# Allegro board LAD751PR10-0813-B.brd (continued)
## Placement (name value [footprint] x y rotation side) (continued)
CG267  22U_0603_6.3V6M  [C_0603]  271.98 90.9 180 top
CG268  22U_0603_6.3V6M  [C_0603]  263.22 55.21 270 bottom
CG269  10U_0603_6.3V6M  [C_0603]  271.41 112.87 180 top
CG270  10U_0603_6.3V6M  [C_0603]  234.9 88.04 90 top
CG271  10U_0603_6.3V6M  [C_0603]  247.21 50.26 0 bottom
CG272  1U_0402_6.3V4Z  [C_0402]  235.53 79.33 90 top
CG273  1U_0402_6.3V4Z  [C_0402]  245.17 50.32 0 bottom
CG274  1U_0402_6.3V4Z  [C_0402]  192.97 68.36 0 bottom
CG275  1U_0402_6.3V4Z  [C_0402]  223.29 77.69 180 top
CG276  1U_0402_6.3V4Z  [C_0402]  190.57 77.2 270 bottom
CG277  1U_0402_6.3V4Z  [C_0402]  193.32 83.34 180 bottom
CG278  22U_0603_6.3V6M  [C_0603]  231.78 54.39 270 bottom
CG279  22U_0603_6.3V6M  [C_0603]  263.22 65.5 90 bottom
CG280  22U_0603_6.3V6M  [C_0603]  263.22 64.48 270 bottom
CG281  10U_0603_6.3V6M  [C_0603]  285.19 78.39 270 bottom
CG282  10U_0603_6.3V6M  [C_0603]  254.33 50.2 180 bottom
CG283  10U_0603_6.3V6M  [C_0603]  204.22 86.27 0 bottom
CG284  1U_0402_6.3V4Z  [C_0402]  193.67 102.39 0 bottom
CG285  1U_0402_6.3V4Z  [C_0402]  196.36 68.36 180 bottom
CG286  1U_0402_6.3V4Z  [C_0402]  224.24 50.32 180 bottom
CG287  1U_0402_6.3V4Z  [C_0402]  196.36 102.39 180 bottom
CG288  22U_0603_6.3V6M  [C_0603]  194.19 113.06 180 bottom
CG289  10U_0603_6.3V6M  [C_0603]  192.62 109.54 270 bottom
CG290  10U_0603_6.3V6M  [C_0603]  230.26 116.68 90 top
CG291  4.7U_0402_6.3V6M  [C_0402]  227.21 108.82 270 top
CG292  1U_0402_6.3V4Z  [C_0402]  192.78 111.13 90 bottom
CG293  0.1U_0201_6.3V6K  [C_0201]  194.18 108.77 270 bottom
CG294  0.1U_0201_6.3V6K  [C_0201]  192.3 110.45 180 bottom
CG295  4.7U_0402_6.3V6M  [C_0402]  220.54 102.19 90 top
CG296  4.7U_0402_6.3V6M  [C_0402]  218.06 105.63 0 top
CG297  4.7U_0402_6.3V6M  [C_0402]  236.8 108.57 270 top
CG298  1U_0402_6.3V4Z  [C_0402]  219.59 102.19 90 top
CG299  1U_0402_6.3V4Z  [C_0402]  221.32 106.9 180 top
CG300  1U_0402_6.3V4Z  [C_0402]  237.88 108.57 270 top
CG301  0.1U_0201_6.3V6K  [C_0201]  239.02 110.55 90 top
CG302  0.1U_0201_6.3V6K  [C_0201]  220.48 104.71 90 top
CG303  0.1U_0201_6.3V6K  [C_0201]  221.59 108.36 0 top
CG304  0.1U_0201_6.3V6K  [C_0201]  239.72 108.4 270 top
CG305  0.1U_0201_6.3V6K  [C_0201]  223.24 104.81 0 top
CG306  0.1U_0201_6.3V6K  [C_0201]  219.85 104.71 90 top
CG307  0.1U_0201_6.3V6K  [C_0201]  220.48 109.15 90 top
CG308  0.1U_0402_10V7K  [C_0402]  241.87 113.25 90 top
CG309  0.1U_0402_10V7K  [C_0402]  242.96 113.39 0 top
CG310  1U_0402_6.3V6K  [C_0402]  230.3 107.93 180 top
CG311  4.7U_0603_6.3V6M  [C_0603]  245.14 111.96 90 top
CG312  0.1U_0402_10V7K  [C_0402]  218.7 102.2 90 top
CG313  0.01U_0402_16V7K  [C_0402]  276.32 101.4 270 top
CG314  0.01U_0402_16V7K  [C_0402]  272.74 102.56 90 top
CG315  0.01U_0402_16V7K  [C_0402]  264.85 60.31 270 bottom
CG316  0.01U_0402_16V7K  [C_0402]  274.6 66.67 180 top
CG317  0.01U_0402_16V7K  [C_0402]  229.4 62.95 180 top
CG318  0.01U_0402_16V7K  [C_0402]  230.93 60.29 0 top
CG320  10U_0402_6.3V6M  [C_0402]  195.03 109.07 270 bottom
CG322  1U_0402_6.3V6K  [C_0402]  196.58 104.03 90 bottom
CG323  0.1U_0402_16V7K  [C_0402]  196.57 106.75 270 bottom
CG324  22U_0402_6.3V6M  [C_0402]  277.73 113.84 270 top
CG325  10U_0402_6.3V4Z  [C_0402]  271.36 109.7 180 top
CG326  10U_0402_6.3V4Z  [C_0402]  270.95 104.26 180 top
CG327  10U_0402_6.3V4Z  [C_0402]  279.32 110.45 180 top
CG328  1U_0402_6.3V4Z  [C_0402]  270.52 117.71 0 top
CG329  1U_0402_6.3V4Z  [C_0402]  273.8 113 0 top
CG330  1U_0402_6.3V4Z  [C_0402]  281.1 110.48 180 top
CG331  1U_0402_6.3V4Z  [C_0402]  273.8 112.06 0 top
CG332  1U_0402_6.3V4Z  [C_0402]  271.36 110.64 180 top
CG333  1U_0402_6.3V4Z  [C_0402]  278.33 104.32 0 top
CG334  1U_0402_6.3V4Z  [C_0402]  281.64 100.16 180 top
CG335  1U_0402_6.3V4Z  [C_0402]  273.03 93.97 0 top
CG336  1U_0402_6.3V4Z  [C_0402]  278.46 99.93 180 top
CG337  1U_0402_6.3V4Z  [C_0402]  272.27 85.99 0 top
CG338  1U_0402_6.3V4Z  [C_0402]  278.46 99.04 180 top
CG339  1U_0402_6.3V4Z  [C_0402]  278.98 93.12 180 top
CG340  1U_0402_6.3V4Z  [C_0402]  271.28 93.99 0 top
CG341  1U_0402_6.3V4Z  [C_0402]  269.54 93.99 0 top
CG342  1U_0402_6.3V4Z  [C_0402]  272.23 98.75 180 top
CG343  1U_0402_6.3V4Z  [C_0402]  270.46 98.74 180 top
CG344  22U_0402_6.3V6M  [C_0402]  262.48 53.7 270 top
CG345  10U_0402_6.3V4Z  [C_0402]  248.71 57.07 270 top
CG346  10U_0402_6.3V4Z  [C_0402]  248.69 54.4 90 top
CG347  10U_0402_6.3V4Z  [C_0402]  256.55 53.74 270 top
CG348  1U_0402_6.3V4Z  [C_0402]  259.67 50.58 180 top
CG349  1U_0402_6.3V4Z  [C_0402]  254.64 53.65 270 top
CG350  1U_0402_6.3V4Z  [C_0402]  256.37 55.76 270 top
CG351  1U_0402_6.3V4Z  [C_0402]  254.63 56.32 90 top
CG352  1U_0402_6.3V4Z  [C_0402]  257.31 64.29 270 top
CG353  1U_0402_6.3V4Z  [C_0402]  253.88 61.69 270 top
CG354  1U_0402_6.3V4Z  [C_0402]  272.12 82.71 0 top
CG355  1U_0402_6.3V4Z  [C_0402]  270.66 82.72 180 top
CG356  1U_0402_6.3V4Z  [C_0402]  269.57 78.07 0 top
CG357  1U_0402_6.3V4Z  [C_0402]  271.4 78.1 0 top
CG358  1U_0402_6.3V4Z  [C_0402]  280.93 69.5 0 top
CG359  1U_0402_6.3V4Z  [C_0402]  271.48 75.66 180 top
CG360  1U_0402_6.3V4Z  [C_0402]  277.61 73.22 270 top
CG361  1U_0402_6.3V4Z  [C_0402]  272.56 69.92 180 top
CG362  1U_0402_6.3V4Z  [C_0402]  275.17 73.12 90 top
CG363  1U_0402_6.3V4Z  [C_0402]  273.22 74.77 180 top
CG364  22U_0402_6.3V6M  [C_0402]  219.07 50.54 180 top
CG365  10U_0402_6.3V4Z  [C_0402]  219.77 61.75 270 top
CG366  10U_0402_6.3V4Z  [C_0402]  215.64 50.46 0 top
CG367  10U_0402_6.3V4Z  [C_0402]  221.38 62.55 270 top
CG368  1U_0402_6.3V4Z  [C_0402]  229.28 64.76 270 bottom
CG369  1U_0402_6.3V4Z  [C_0402]  220.09 55.87 90 top
CG370  1U_0402_6.3V4Z  [C_0402]  215.64 51.37 0 top
CG371  1U_0402_6.3V4Z  [C_0402]  213.79 50.49 0 top
CG372  1U_0402_6.3V4Z  [C_0402]  213.79 51.4 0 top
CG373  1U_0402_6.3V4Z  [C_0402]  223.68 57.84 0 top
CG374  1U_0402_6.3V4Z  [C_0402]  231.82 58.5 90 top
CG375  1U_0402_6.3V4Z  [C_0402]  232.23 64.57 90 top
CG376  1U_0402_6.3V4Z  [C_0402]  232.43 57.25 270 top
CG377  1U_0402_6.3V4Z  [C_0402]  235.1 50.6 180 top
CG378  1U_0402_6.3V4Z  [C_0402]  238.71 62.58 270 top
CG379  1U_0402_6.3V4Z  [C_0402]  238.64 53.77 270 top
CG380  1U_0402_6.3V4Z  [C_0402]  238.72 56.25 270 top
CG381  1U_0402_6.3V4Z  [C_0402]  236.51 57.87 180 top
CG382  1U_0402_6.3V4Z  [C_0402]  231.94 55.38 90 bottom
CG383  1U_0402_6.3V4Z  [C_0402]  232 62.01 270 bottom
CG384  0.1U_0402_10V7K  [C_0402]  194.37 104.15 0 top
CG385  10U_0402_6.3V6M  [C_0402]  197.46 106.75 270 bottom
CG386  0.1U_0402_10V7K  [C_0402]  196.74 114.51 0 bottom
CG387  0.01U_0402_16V7K  [C_0402]  199.25 86.05 90 bottom
CG388  0.01U_0402_16V7K  [C_0402]  200.12 84.49 270 bottom
CG389  22U_0402_6.3V6M  [C_0402]  191.31 99 270 top
CG390  10U_0402_6.3V4Z  [C_0402]  205.23 84.3 0 bottom
CG391  10U_0402_6.3V4Z  [C_0402]  194.64 86.9 180 bottom
CG392  10U_0402_6.3V4Z  [C_0402]  205.23 85.2 0 bottom
CG393  1U_0402_6.3V4Z  [C_0402]  200.87 102.39 180 top
CG394  1U_0402_6.3V4Z  [C_0402]  195.88 95.69 0 top
CG395  1U_0402_6.3V4Z  [C_0402]  202.92 101.42 180 top
CG396  1U_0402_6.3V4Z  [C_0402]  193.93 95.76 180 top
CG397  1U_0402_6.3V4Z  [C_0402]  202.61 94 0 top
CG398  1U_0402_6.3V4Z  [C_0402]  204.48 94.15 0 top
CG399  1U_0402_6.3V4Z  [C_0402]  194.65 67.95 180 top
CG400  1U_0402_6.3V4Z  [C_0402]  190.62 78.99 0 top
CG401  1U_0402_6.3V4Z  [C_0402]  204.9 68.62 0 top
CG402  1U_0402_6.3V4Z  [C_0402]  196.92 75.11 180 top
CG403  1U_0402_6.3V4Z  [C_0402]  197.95 78.77 90 top
CG404  1U_0402_6.3V4Z  [C_0402]  206.75 73.69 180 top
CG405  1U_0402_6.3V4Z  [C_0402]  191.36 73.49 270 top
CG406  1U_0402_6.3V4Z  [C_0402]  201.74 68.73 0 top
CG407  1U_0402_6.3V4Z  [C_0402]  204.02 68.64 90 top
CG408  1U_0402_6.3V4Z  [C_0402]  198.05 68.43 90 top
CG410  22U_0402_6.3V6M  [C_0402]  267.88 90.14 270 top
CG411  22U_0402_6.3V6M  [C_0402]  268.75 90.16 270 top
CG412  22U_0402_6.3V6M  [C_0402]  273.63 91.54 0 top
CG413  10U_0402_6.3V4Z  [C_0402]  278.51 95.66 180 top
CG414  10U_0402_6.3V4Z  [C_0402]  278.45 100.82 180 top
CG415  10U_0402_6.3V4Z  [C_0402]  279.82 93.11 0 top
CG416  1U_0402_6.3V4Z  [C_0402]  270.46 99.64 180 top
CG417  1U_0402_6.3V4Z  [C_0402]  268.63 94.74 90 top
CG418  1U_0402_6.3V4Z  [C_0402]  272.26 85.07 0 top
CG419  1U_0402_6.3V4Z  [C_0402]  271.78 91.95 180 top
CG420  1U_0402_6.3V4Z  [C_0402]  268.54 97.99 270 top
CG421  1U_0402_6.3V4Z  [C_0402]  276.7 94.79 0 top
CG422  1U_0402_6.3V4Z  [C_0402]  273.06 93.08 180 top
CG423  1U_0402_6.3V4Z  [C_0402]  275.64 90.04 90 top
CG424  1U_0402_6.3V4Z  [C_0402]  276.56 90.04 90 top
CG425  1U_0402_6.3V4Z  [C_0402]  269.55 93.01 0 top
CG426  22U_0402_6.3V6M  [C_0402]  259.69 49.69 180 top
CG427  22U_0402_6.3V6M  [C_0402]  263.36 53.71 270 top
CG428  22U_0402_6.3V6M  [C_0402]  255.51 56.32 90 top
CG429  10U_0402_6.3V4Z  [C_0402]  250.62 54.55 270 top
CG430  10U_0402_6.3V4Z  [C_0402]  254.05 50.67 180 top
CG431  10U_0402_6.3V4Z  [C_0402]  256.31 65.26 0 top
CG432  1U_0402_6.3V4Z  [C_0402]  254.69 64.03 90 top
CG433  1U_0402_6.3V4Z  [C_0402]  249.34 63.25 270 top
CG434  1U_0402_6.3V4Z  [C_0402]  263.34 55.51 270 top
CG435  1U_0402_6.3V4Z  [C_0402]  254.77 61.69 270 top
CG436  1U_0402_6.3V4Z  [C_0402]  257.21 50.63 180 top
CG437  1U_0402_6.3V4Z  [C_0402]  257.23 49.74 180 top
CG438  1U_0402_6.3V4Z  [C_0402]  258.83 60.2 180 top
CG439  1U_0402_6.3V4Z  [C_0402]  258.73 57.84 0 top
CG440  1U_0402_6.3V4Z  [C_0402]  254.06 49.78 180 top
CG441  1U_0402_6.3V4Z  [C_0402]  248.45 63.27 270 top
CG442  22U_0402_6.3V6M  [C_0402]  228.38 53.66 270 top
CG443  22U_0402_6.3V6M  [C_0402]  221.42 55.72 90 top
CG444  22U_0402_6.3V6M  [C_0402]  229.28 53.66 270 top
CG445  10U_0402_6.3V4Z  [C_0402]  227.48 55.45 270 top
CG446  10U_0402_6.3V4Z  [C_0402]  228.37 55.43 270 top
CG447  10U_0402_6.3V4Z  [C_0402]  227.5 53.66 270 top
CG448  1U_0402_6.3V4Z  [C_0402]  224.23 50.59 180 top
CG449  1U_0402_6.3V4Z  [C_0402]  222.3 57.51 180 top
CG450  1U_0402_6.3V4Z  [C_0402]  221.32 49.64 0 top
CG451  1U_0402_6.3V4Z  [C_0402]  221.32 50.54 0 top
CG452  1U_0402_6.3V4Z  [C_0402]  220.54 53.99 90 top
CG453  1U_0402_6.3V4Z  [C_0402]  220.35 51.9 180 top
CG454  1U_0402_6.3V4Z  [C_0402]  224.24 49.69 180 top
CG455  1U_0402_6.3V4Z  [C_0402]  221 64.03 90 top
CG456  1U_0402_6.3V4Z  [C_0402]  228.14 57.99 180 top
CG457  1U_0402_6.3V4Z  [C_0402]  221.42 53.98 90 top
CG458  22U_0402_6.3V6M  [C_0402]  201.7 94.06 270 top
CG459  22U_0402_6.3V6M  [C_0402]  197.18 102.01 270 top
CG460  22U_0402_6.3V6M  [C_0402]  192.02 101.78 0 top
CG461  10U_0402_6.3V4Z  [C_0402]  193.96 94.81 180 top
CG462  10U_0402_6.3V4Z  [C_0402]  204.26 95.45 0 top
CG463  10U_0402_6.3V4Z  [C_0402]  201.95 95.68 180 top
CG464  1U_0402_6.3V4Z  [C_0402]  200.14 96.62 270 top
CG465  1U_0402_6.3V4Z  [C_0402]  201.76 102.41 90 top
CG466  1U_0402_6.3V4Z  [C_0402]  202.8 102.31 90 top
CG467  1U_0402_6.3V4Z  [C_0402]  204.85 102.64 180 top
CG468  1U_0402_6.3V4Z  [C_0402]  190.33 91.1 270 top
CG469  1U_0402_6.3V4Z  [C_0402]  192.16 93.89 90 top
CG470  1U_0402_6.3V4Z  [C_0402]  191.3 96.31 90 top
CG471  1U_0402_6.3V4Z  [C_0402]  200.87 103.28 180 top
CG472  1U_0402_6.3V4Z  [C_0402]  198.61 92.64 0 top
CG473  1U_0402_6.3V4Z  [C_0402]  198.54 94.93 180 top
CG474  0.1U_0402_16V4Z  [C_0402]  197.89 111.45 0 top
CG475  0.1U_0402_16V4Z  [C_0402]  196.76 104.46 270 top
CG476  0.1U_0201_6.3V6K  [C_0201]  314.31 60.32 270 top
CG478  0.1U_0201_6.3V6K  [C_0201]  277.36 155.16 90 top
CG479  0.1U_0201_6.3V6K  [C_0201]  280.35 161.33 0 top
CG480  0.1U_0201_6.3V6K  [C_0201]  275.69 147.77 270 top
CG481  2200P_0402_25V7K  [C_0402]  281.64 162.54 180 top
CG482  0.047U_0402_16V4Z  [C_0402]  277.92 162.91 270 top
CG483  0.1U_0201_6.3V6K  [C_0201]  281.21 144.11 270 top
CG487  0.1U_0402_16V7K  [C_0402]  193.16 109.54 180 top
CH3  0.1U_0402_10V7K  [C_0402]  204.15 23.88 270 top
CH4  0.1U_0402_10V7K  [C_0402]  215.31 33.51 270 top
CH45  8.2P_0402_50V  [C_0402]  219.66 37.08 90 bottom
CH46  8.2P_0402_50V  [C_0402]  219.66 36.15 270 bottom
CH47  15P_0402_50V  [C_0402]  193.47 43.49 180 bottom
CH48  15P_0402_50V  [C_0402]  194.35 43.49 0 bottom
CH49  0.1U_0402_16V7K  [C_0402]  229.04 14.32 0 bottom
CH52  1U_0603_10V6K~D  [C_0603]  216.37 32.23 270 top
CH53  1U_0603_10V6K~D  [C_0603]  216.68 41.81 0 top
CH70  0.1U_0402_10V7K  [C_0402]  214.65 27.01 180 top
CH80  1U_0402_6.3V6K~D  [C_0402]  212.61 29.06 180 top
CH82  1U_0402_6.3V6K~D  [C_0402]  203.73 32.84 90 top
CH100  0.022U_0402_25V7K  [C_0402]  152.66 37.58 0 top
CH101  0.022U_0402_25V7K  [C_0402]  155.34 53.57 90 top
CH102  10U_0603_6.3V6M~D  [C_0603]  168.05 105.17 270 top
CH103  10U_0603_6.3V6M~D  [C_0603]  168.05 107.58 270 top
CH104  10U_0603_6.3V6M~D  [C_0603]  167.94 109.98 90 top
CH105  1U_0402_6.3V6K~D  [C_0402]  172.5 114.54 0 top
CH106  1U_0402_6.3V6K~D  [C_0402]  172.5 115.42 0 top
CH107  1U_0402_6.3V6K~D  [C_0402]  167.98 113.21 0 top
CH108  1U_0402_6.3V6K~D  [C_0402]  168.19 114.51 180 top
CH109  1U_0402_6.3V6K~D  [C_0402]  169.48 114.84 0 top
CH110  1U_0402_6.3V6K~D  [C_0402]  167.9 112.31 0 top
CH118  22U_0603_6.3V6M  [C_0603]  146.02 100.47 90 top
CH119  10U_0603_6.3V6M~D  [C_0603]  150.78 99.52 90 top
CH120  22U_0603_6.3V6M  [C_0603]  171.46 99.09 0 top
CH121  22U_0603_6.3V6M  [C_0603]  148.65 79.51 0 top
CH122  10U_0603_6.3V6M~D  [C_0603]  152.49 99.84 90 top
CH123  10U_0603_6.3V6M~D  [C_0603]  148.65 78.24 0 top
CH124  22U_0603_6.3V6M  [C_0603]  144.37 100.47 90 top
CH125  10U_0603_6.3V6M~D  [C_0603]  156.13 99.18 90 top
CH126  10U_0603_6.3V6M~D  [C_0603]  167.9 95.6 90 top
CH127  10U_0603_6.3V6M~D  [C_0603]  165.25 99.77 90 top
CH128  10U_0603_6.3V6M~D  [C_0603]  148.65 76.97 0 top
CH129  22U_0805_6.3V6M~D  [C_0805]  168.15 79.25 0 top
CH130  22U_0805_6.3V6M~D  [C_0805]  168.15 77.54 0 top
CH131  22U_0805_6.3V6M~D  [C_0805]  153.57 77.34 180 top
CH132  22U_0805_6.3V6M~D  [C_0805]  153.57 79.18 180 top
CH173  0.1U_0402_10V7K  [C_0402]  212.61 28.17 180 top
CH174  0.1U_0402_10V  [C_0402]  210.27 35.43 90 top
CH175  0.1U_0402_10V  [C_0402]  214.9 43.11 90 bottom
CH176  1U_0402_6.3V6K~D  [C_0402]  214.14 25.5 180 top
CH177  22U_0805_6.3V6M~D  [C_0805]  203.44 42.07 0 bottom
CH178  22U_0805_6.3V6M~D  [C_0805]  200.33 42.32 0 bottom
CH179  1U_0402_6.3V6K~D  [C_0402]  199.34 41.8 90 bottom
CH180  1U_0402_6.3V6K~D  [C_0402]  198.64 28.4 90 top
CH181  22U_0805_6.3V6M~D  [C_0805]  193.34 26 180 top
CH182  22U_0805_6.3V6M~D  [C_0805]  193.34 27.77 180 top
CH183  1U_0402_6.3V6K~D  [C_0402]  202.19 26.91 270 top
CH184  22U_0805_6.3V6M~D  [C_0805]  193.34 29.53 180 top
CH185  1U_0402_6.3V6K~D  [C_0402]  206.03 30.57 180 top
CH186  0.1U_0402_10V7K  [C_0402]  213.9 30.49 180 top
CH187  1U_0402_6.3V6K~D  [C_0402]  216.85 40.74 0 top
CH188  1U_0402_6.3V6K~D  [C_0402]  206.14 33.79 90 top
CH189  0.1U_0402_10V7K  [C_0402]  210.27 37.78 90 top
CH190  0.1U_0402_10V7K  [C_0402]  206.01 19.6 270 top
CH191  0.1U_0402_10V7K  [C_0402]  209.57 19.28 270 top
CH192  0.1U_0402_10V7K  [C_0402]  215.46 16.45 0 top
CH193  0.1U_0402_16V7K~D  [C_0402]  172.79 100.48 90 top
CH194  0.1U_0402_16V7K~D  [C_0402]  130.9 114.97 180 top
CH195  0.1U_0402_16V7K~D  [C_0402]  132.33 115.48 0 top
CH197  0.1U_0402_10V7K  [C_0402]  125.57 75.89 270 top
CH200  0.1U_0402_10V7K  [C_0402]  213 23.2 270 top
CH201  0.1U_0201_6.3V6K  [C_0201]  216.42 22.28 90 top
CH202  0.22U_0201_6.3V  [C_0201]  247.66 9.39 90 top
CH203  0.22U_0201_6.3V  [C_0201]  248.29 9.39 90 top
CH204  0.22U_0201_6.3V  [C_0201]  329.87 36.23 180 top
CH205  0.22U_0201_6.3V  [C_0201]  329.87 35.59 180 top
CH206  0.22U_0201_6.3V  [C_0201]  331.26 37.12 180 top
CH207  0.22U_0201_6.3V  [C_0201]  331.26 36.48 180 top
CH208  0.22U_0201_6.3V  [C_0201]  250.07 9.39 90 top
CH209  0.22U_0201_6.3V  [C_0201]  250.71 9.39 90 top
CH210  0.22U_0201_6.3V  [C_0201]  237.92 7.78 180 top
CH211  0.22U_0201_6.3V  [C_0201]  237.92 8.41 180 top
CH212  0.22U_0201_6.3V  [C_0201]  239.57 11.08 180 top
CH213  0.22U_0201_6.3V  [C_0201]  239.57 10.45 180 top
CH214  0.22U_0201_6.3V  [C_0201]  269.38 12.24 180 bottom
CH215  0.22U_0201_6.3V  [C_0201]  269.38 11.59 180 bottom
CH216  0.22U_0201_6.3V  [C_0201]  268.78 15.73 180 bottom
CH217  0.22U_0201_6.3V  [C_0201]  268.78 15.09 180 bottom
CH218  0.22U_0201_6.3V  [C_0201]  269.1 20.21 90 bottom
CH219  0.22U_0201_6.3V  [C_0201]  268.46 20.21 90 bottom
CH220  0.22U_0201_6.3V  [C_0201]  268.18 17.2 0 bottom
CH221  0.22U_0201_6.3V  [C_0201]  268.18 17.84 0 bottom
CI38  0.1U_0402_10V6K  [C_0402]  165.68 173.77 90 bottom
CI39  0.1U_0402_10V6K  [C_0402]  166.57 173.77 90 bottom
CL1  0.1U_0402_16V7K  [C_0402]  268.56 163.67 180 bottom
CL2  0.1U_0402_16V7K  [C_0402]  268.56 162.78 180 bottom
CL3  0.1U_0402_16V7K  [C_0402]  271.8 165.88 90 bottom
CL4  0.1U_0402_16V7K  [C_0402]  272.69 165.88 90 bottom
CL5  1U_0402_6.3V6K~D  [C_0402]  275.34 160.46 180 top
CL6  0.1U_0402_16V7K~D  [C_0402]  275.34 159.57 180 top
CL7  0.1U_0402_16V7K~D  [C_0402]  267.38 159.66 180 bottom
CL8  18P_0402_50V8J  [C_0402]  277.8 161 180 bottom
CL9  22P_0402_50V8J  [C_0402]  278.22 162.47 180 bottom
CL11  1000P_0402_50V7K~D  [C_0402]  276.63 165.13 0 bottom
CL12  0.1U_0402_16V7K~D  [C_0402]  269.59 167.02 180 top
CL13  1U_0402_6.3V6K~D  [C_0402]  269.59 166.14 180 top
CL14  10U_0603_6.3V6M~D  [C_0603]  269.77 168.1 180 top
CL15  10U_0603_6.3V6M~D  [C_0603]  269.77 169.37 180 top
CL16  0.1U_0402_16V7K~D  [C_0402]  272.54 157.79 90 top
CL17  1U_0402_6.3V6K~D  [C_0402]  274.3 157.79 90 top
CL18  1U_0402_6.3V6K~D  [C_0402]  275.34 161.35 180 top
CL19  0.1U_0402_16V7K~D  [C_0402]  275.34 162.24 180 top
CL20  0.1U_0402_16V7K~D  [C_0402]  271.6 164.6 270 top
CL21  1U_0402_6.3V6K~D  [C_0402]  270.71 164.6 270 top
CL22  4.7U_0603_6.3V6K~D  [C_0603]  272.51 165.51 90 top
CL23  0.1U_0402_16V7K~D  [C_0402]  269.82 164.6 270 top
CL24  0.1U_0402_16V7K~D  [C_0402]  273.43 157.79 90 top
CL25  0.1U_0402_16V7K~D  [C_0402]  271.65 157.79 90 top
CL27  470P_0402_50V7K  [C_0402]  242.71 170.03 270 top
CL28  470P_0402_50V7K  [C_0402]  263.47 158.41 270 top
CL29  470P_0402_50V7K  [C_0402]  264.36 158.41 270 top
CL30  10P_1808_3KV7K~D  [C_1808]  263.03 158.66 90 bottom
CL31  470P_0402_50V7K  [C_0402]  266.12 159.8 0 top
CL32  1000P_0402_50V7K~D  [C_0402]  250.83 156.76 270 top
CL33  0.1U_0402_16V7K~D  [C_0402]  247.91 155.85 90 top
CL34  1000P_0402_50V7K~D  [C_0402]  247.02 156.76 270 top
CL35  0.1U_0402_16V7K~D  [C_0402]  249.94 155.85 90 top
CL36  1000P_0402_50V7K~D  [C_0402]  254.96 156.76 270 top
CL37  0.1U_0402_16V7K~D  [C_0402]  255.85 155.85 90 top
CL38  1000P_0402_50V7K~D  [C_0402]  257.44 156.76 270 top
CL39  0.1U_0402_16V7K~D  [C_0402]  258.33 155.85 90 top
CL40  4.7U_0805_10V4Z  [C_0805]  269.97 171.67 180 bottom
CL41  0.1U_0402_16V7K  [C_0402]  271.03 171.22 90 bottom
CL42  0.1U_0402_16V7K  [C_0402]  266.96 170.29 270 bottom
CL43  1U_0402_6.3V6K~D  [C_0402]  273.38 164.6 270 top
CL44  0.1U_0402_16V7K~D  [C_0402]  272.49 164.6 270 top
CLRP1  SHORT PADS  [SHORTPADS]  173.94 34.07 90 bottom
CM9  0.1U_0402_10V7K  [C_0402]  134.11 160.39 90 bottom
CM10  0.1U_0402_10V7K  [C_0402]  302.88 41.99 90 top
CM11  4.7U_0805_10V4Z  [C_0805]  314.23 42.07 180 top
CM12  22U_0603_6.3V6M~D  [C_0603]  301.8 40.79 90 top
CM13  0.1U_0402_10V7K~D  [C_0402]  300.72 40.78 90 top
CM14  22U_0603_6.3V6M~D  [C_0603]  315.54 41.37 90 top
CM15  0.1U_0402_10V7K~D  [C_0402]  315.73 40.18 270 top
CM16  0.1U_0402_10V7K  [C_0402]  172.4 159.42 0 bottom
CM17  0.1U_0402_10V7K  [C_0402]  172.4 160.31 0 bottom
CM18  0.1U_0402_10V7K  [C_0402]  168.41 161.37 90 bottom
CM19  22U_0603_6.3V6M  [C_0603]  164.16 160.5 270 bottom
CM20  0.1U_0402_10V7K  [C_0402]  168.34 152.36 270 bottom
CM21  1U_0402_6.3V  [C_0402]  165.99 152.36 270 bottom
CM23  0.1U_0402_10V7K  [C_0402]  162.25 174.49 270 bottom
CM29  10U_0603_6.3V6M  [C_0603]  125.98 151.39 0 top
CM30  1U_0402_6.3V  [C_0402]  125.23 155.2 180 bottom
CM31  10U_0603_6.3V6M  [C_0603]  125.98 153.17 0 top
CM32  0.1U_0402_10V7K  [C_0402]  131.12 151.47 270 bottom
CM33  1U_0402_6.3V  [C_0402]  125.23 156.09 180 bottom
CM34  0.1U_0402_10V7K  [C_0402]  138.43 155.54 0 bottom
CM35  0.1U_0402_10V7K  [C_0402]  129.6 151.47 270 bottom
CM36  0.1U_0402_10V7K  [C_0402]  130.74 160.39 90 bottom
CM62  0.22U_0201_6.3V  [C_0201]  133.22 148.65 90 bottom
CM63  0.22U_0201_6.3V  [C_0201]  132.97 150.55 90 bottom
CM64  0.22U_0201_6.3V  [C_0201]  136.9 148.65 90 bottom
CM65  0.22U_0201_6.3V  [C_0201]  136.01 148.65 90 bottom
CM66  0.22U_0201_6.3V  [C_0201]  132.08 150.55 90 bottom
CM67  0.22U_0201_6.3V  [C_0201]  135.57 150.55 90 bottom
CM68  0.22U_0201_6.3V  [C_0201]  134.11 148.65 90 bottom
CM69  0.22U_0201_6.3V  [C_0201]  134.68 150.55 90 bottom
CM70  0.1U_0402_10V7K  [C_0402]  149.61 170.92 270 bottom
CM98  0.01U_0402_16V7K  [C_0402]  163.36 162.85 180 bottom
CM99  0.01U_0402_16V7K  [C_0402]  163.36 161.68 180 bottom
CN9  1U_0402_10V6K  [C_0402]  312.81 39.28 90 top
CN23  0.1U_0402_16V7K  [C_0402]  314.32 37.69 180 top
CN24  0.1U_0402_16V7K  [C_0402]  314.32 36.66 180 top
CN25  1U_0402_10V6K  [C_0402]  316.67 36.96 0 top
CPU1  SKL-H_BGA1440  [SKL-H_BGA_1440P-T]  172.98 93.59 270 bottom
CS1  10U_0603_25V6M  [C_0603]  127.45 10.13 270 top
CS2  10U_0603_6.3V6M  [C_0603]  183.99 62.45 180 top
CS5  1000P_0402_50V7K~D  [C_0402]  125.48 10.14 270 top
CS6  0.1U_0402_25V6K~D  [C_0402]  126.37 10.14 270 top
CS7  0.1U_0402_16V4Z  [C_0402]  182.58 66.2 180 top
CS16  22U_0402_6.3V6M  [C_0402]  125.68 11.45 90 top
CT1  0.22U_0201_6.3V  [C_0201]  188.35 162.61 180 top
CT2  0.22U_0201_6.3V  [C_0201]  188.35 163.18 180 top
CT3  0.22U_0201_6.3V  [C_0201]  188.35 160.32 180 top
CT4  0.22U_0201_6.3V  [C_0201]  188.35 164.32 180 top
CT5  0.22U_0201_6.3V  [C_0201]  188.35 166.61 180 top
CT6  0.1U_0201_6.3V6K  [C_0201]  177.42 157.43 90 top
CT7  0.1U_0201_6.3V6K  [C_0201]  177.99 157.43 90 top
CT8  0.1U_0201_6.3V6K  [C_0201]  179.14 157.43 90 top
CT9  0.1U_0201_6.3V6K  [C_0201]  178.57 157.43 90 top
CT10  0.1U_0201_6.3V6K  [C_0201]  180.28 157.43 90 top
CT11  0.1U_0201_6.3V6K  [C_0201]  181.42 157.43 90 top
CT12  0.22U_0201_6.3V  [C_0201]  188.35 163.75 180 top
CT13  0.22U_0201_6.3V  [C_0201]  188.35 162.04 180 top
CT14  0.22U_0201_6.3V  [C_0201]  188.35 161.47 180 top
CT15  0.22U_0201_6.3V  [C_0201]  188.35 159.75 180 top
CT16  0.22U_0201_6.3V  [C_0201]  188.35 160.89 180 top
CT18  0.22U_0201_6.3V  [C_0201]  188.35 164.9 180 top
CT21  0.22U_0201_6.3V  [C_0201]  188.35 167.18 180 top
CT23  0.1U_0201_6.3V6K  [C_0201]  179.71 157.43 90 top
CT24  0.1U_0201_6.3V6K  [C_0201]  180.85 157.43 90 top
CT25  0.1U_0201_6.3V6K  [C_0201]  179.39 152.69 90 bottom
CT26  0.1U_0201_6.3V6K  [C_0201]  178.82 152.69 90 bottom
CT27  0.1U_0201_6.3V6K  [C_0201]  182.57 157.43 90 top
CT28  0.1U_0201_6.3V6K  [C_0201]  182 157.43 90 top
CT29  0.1U_0201_6.3V6K  [C_0201]  183.71 157.43 90 top
CT30  0.1U_0201_6.3V6K  [C_0201]  183.14 157.43 90 top
CT31  0.1U_0201_6.3V6K  [C_0201]  184.85 157.43 90 top
CT32  0.1U_0201_6.3V6K  [C_0201]  184.28 157.43 90 top
CT33  0.1U_0201_6.3V6K  [C_0201]  186 157.43 90 top
CT34  0.1U_0201_6.3V6K  [C_0201]  185.42 157.43 90 top
CT35  0.1U_0201_6.3V6K  [C_0201]  181.35 152.69 90 bottom
CT36  0.1U_0201_6.3V6K  [C_0201]  181.95 152.68 90 bottom
CT37  12P_0402_50V8J  [C_0402]  190.84 170.34 180 top
CT38  12P_0402_50V8J  [C_0402]  190.52 168.82 180 top
CT39  0.22U_0201_6.3V  [C_0201]  183.15 172.68 270 top
CT40  0.22U_0201_6.3V  [C_0201]  182.58 172.68 270 top
CT41  0.22U_0201_6.3V  [C_0201]  184.04 172.68 270 top
CT42  0.22U_0201_6.3V  [C_0201]  184.61 172.68 270 top
CT43  0.1U_0201_6.3V6K  [C_0201]  182.62 159.67 90 bottom
CT44  0.1U_0201_6.3V6K  [C_0201]  182.05 159.67 90 bottom
CT45  0.1U_0201_6.3V6K  [C_0201]  188.67 154.41 270 bottom
CT46  0.1U_0201_6.3V6K  [C_0201]  178.75 162.54 270 bottom
CT47  1U_0201_6.3V6M  [C_0201]  178.11 167.68 270 bottom
CT48  1U_0201_6.3V6M  [C_0201]  181.9 163.74 0 bottom
CT49  1U_0201_6.3V6M  [C_0201]  176.43 172.12 180 top
CT50  10U_0402_6.3V6M  [C_0402]  176.87 172.88 180 top
CT51  10U_0402_6.3V6M  [C_0402]  176.87 173.77 180 top
CT52  10U_0402_6.3V6M  [C_0402]  176.87 174.66 180 top
CT53  10U_0402_6.3V6M  [C_0402]  177.73 174.66 0 top
CT54  1U_0201_6.3V6M  [C_0201]  180.03 165.04 270 bottom
CT55  1U_0201_6.3V6M  [C_0201]  184.57 163.8 0 bottom
CT56  1U_0201_6.3V6M  [C_0201]  187.18 158.05 180 top
CT57  1U_0201_6.3V6M  [C_0201]  175.45 153.02 270 bottom
CT58  1U_0201_6.3V6M  [C_0201]  174.81 153.02 270 bottom
CT59  1U_0201_6.3V6M  [C_0201]  181.29 165.21 270 bottom
CT60  1U_0201_6.3V6M  [C_0201]  181.86 162.53 270 bottom
CT61  1U_0201_6.3V6M  [C_0201]  179.38 165.02 270 bottom
CT62  1U_0201_6.3V6M  [C_0201]  178.6 165.68 180 bottom
CT63  1U_0201_6.3V6M  [C_0201]  179.4 168.6 270 bottom
CT64  1U_0201_6.3V6M  [C_0201]  180.41 169.22 90 bottom
CT65  1U_0201_6.3V6M  [C_0201]  179.84 169.22 90 bottom
CT66  1U_0201_6.3V6M  [C_0201]  180.98 169.22 90 bottom
CT67  1U_0201_6.3V6M  [C_0201]  179.24 169.81 180 bottom
CT68  1U_0201_6.3V6M  [C_0201]  179.24 169.23 180 bottom
CT69  1U_0201_6.3V6M  [C_0201]  181.56 169.22 90 bottom
CT70  1U_0201_6.3V6M  [C_0201]  187.8 157.99 0 top
CT71  1U_0201_6.3V6M  [C_0201]  183.93 164.43 0 bottom
CT72  1U_0201_6.3V6M  [C_0201]  183.12 164.43 180 bottom
CT73  47U_0603_6.3V6M  [C_0603]  173.21 173.14 90 bottom
CT74  47U_0603_6.3V6M  [C_0603]  171.88 173.14 90 bottom
CT75  47U_0603_6.3V6M  [C_0603]  170.54 173.14 90 bottom
CT77  1U_0201_6.3V6M  [C_0201]  183.17 162.57 0 bottom
CT78  1U_0201_6.3V6M  [C_0201]  179.38 162.54 270 bottom
CT79  1U_0201_6.3V6M  [C_0201]  181.29 163.42 90 bottom
CT80  1U_0201_6.3V6M  [C_0201]  180.03 163.25 90 bottom
CT81  10U_0402_6.3V6M  [C_0402]  183.54 168.8 90 bottom
CT82  10U_0402_6.3V6M  [C_0402]  182.65 168.8 90 bottom
CT83  1U_0201_6.3V6M  [C_0201]  181.15 167.16 180 bottom
CT84  1U_0201_6.3V6M  [C_0201]  183.42 166.97 0 bottom
CT85  1U_0201_6.3V6M  [C_0201]  183.97 166.25 270 bottom
CT86  1U_0201_6.3V6M  [C_0201]  182.63 166.33 90 bottom
CT88  0.1U_0402_10V6K  [C_0402]  195.6 163.67 180 top
CT90  22U_0603_6.3V6M  [C_0603]  203.83 158.31 180 bottom
CT91  22U_0603_6.3V6M  [C_0603]  203.83 157.05 180 bottom
CT92  22U_0603_6.3V6M  [C_0603]  204.72 160.15 0 bottom
CT93  22U_0603_6.3V6M  [C_0603]  204.72 161.36 0 bottom
CT94  0.47U_0402_25V6K  [C_0402]  194.9 179.55 180 top
CT95  0.47U_0402_25V6K  [C_0402]  190.31 177.95 0 top
CT96  0.47U_0402_25V6K  [C_0402]  193.18 177.62 0 top
CT97  0.47U_0402_25V6K  [C_0402]  191.28 179.59 180 top
CT98  2.2U_0603_16V6K  [C_0603]  195.97 161.26 180 bottom
CT99  4.7U_0603_10V6K  [C_0603]  197.56 158.02 180 bottom
CT100  4.7U_0603_10V6K  [C_0603]  198.26 165.13 90 top
CT101  1U_0402_6.3V6K  [C_0402]  197.1 164.18 0 top
CT102  1U_0201_6.3V6M  [C_0201]  196.22 167.47 90 top
CT103  10U_0402_6.3V6M  [C_0402]  195.6 162.34 180 bottom
CT104  0.22U_0402_10V4Z  [C_0402]  202.63 167.19 90 bottom
CT106  1U_0603_25V6K  [C_0603]  204.61 160.94 180 top
CT108  0.22U_0201_6.3V  [C_0201]  188.35 166.04 180 top
CT109  0.22U_0201_6.3V  [C_0201]  188.35 165.47 180 top
CT110  0.22U_0201_6.3V  [C_0201]  188.35 167.75 180 top
CT111  0.22U_0201_6.3V  [C_0201]  188.35 168.32 180 top
CT112  220P_0201_25V7K  [C_0201]  202.95 165.78 270 top
CT113  220P_0201_25V7K  [C_0201]  203.75 166.41 270 top
CU2  47U_0805_6.3V6M  [C_0805]  19.92 43.59 0 bottom
CU3  10U_0603_6.3V6M~D  [C_0603]  20.07 42.13 0 bottom
CU6  150U_B15G_6.3VM_R70M  [C_B15G]  20.48 46.07 0 bottom
CU7  0.1U_0402_16V7K  [C_0402]  20.38 41.6 180 top
CU10  47U_0805_6.3V6M  [C_0805]  321.88 20.59 90 top
CU11  10U_0603_6.3V6M~D  [C_0603]  319.97 20.17 180 top
CU12  0.1U_0402_10V7K  [C_0402]  24.16 39.69 0 top
CU13  0.1U_0402_10V7K  [C_0402]  24.16 38.8 0 top
CU16  0.1U_0402_16V7K  [C_0402]  318.46 24.87 180 top
CU17  0.1U_0402_16V7K  [C_0402]  319.39 24.87 0 top
CU18  0.47U_0402_25V6K  [C_0402]  11.06 63.15 90 bottom
CU19  0.47U_0402_25V6K  [C_0402]  11.95 57.31 0 bottom
CU20  0.47U_0402_25V6K  [C_0402]  11.06 62.26 270 bottom
CU21  0.47U_0402_25V6K  [C_0402]  11.06 57.83 270 bottom
CU26  0.1U_0402_16V7K  [C_0402]  27.92 42.74 0 top
CU27  2.2U_0603_6.3V6K  [C_0603]  31.68 44.2 90 top
CU28  0.1U_0402_16V7K  [C_0402]  32.81 47.14 180 top
CU29  0.1U_0402_16V7K  [C_0402]  29.7 46.23 0 top
CU30  0.1U_0402_10V7K  [C_0402]  14.51 61.93 0 top
CU31  0.1U_0402_10V7K  [C_0402]  14.51 62.88 0 top
CU32  2.2U_0603_25V6K  [C_0603]  14.5 54.16 90 bottom
CU33  47U_0603_6.3V6M  [C_0603]  22.63 53.5 90 bottom
CU34  0.1U_0402_16V7K  [C_0402]  22.92 51.15 0 bottom
CU35  0.1U_0402_16V7K  [C_0402]  20.77 50.65 270 bottom
CU37  10U_0805_25V6K  [C_0805]  12.91 54.26 90 bottom
CU38  0.1U_0402_10V7K  [C_0402]  14.74 58.47 0 top
CU39  0.1U_0402_10V7K  [C_0402]  14.74 57.58 0 top
CU40  150U_B15G_6.3VM_R70M  [C_B15G]  13.08 52.08 270 bottom
CU42  47U_0603_6.3V6M  [C_0603]  22.23 50.07 0 bottom
CU44  47U_0603_6.3V6M  [C_0603]  21.41 53.5 90 bottom
CU45  0.1U_0402_10V7K  [C_0402]  321.71 19.58 0 top
CU46  0.1U_0402_10V7K  [C_0402]  315.3 23.49 90 top
CU47  0.1U_0402_10V7K  [C_0402]  21.46 47.59 90 top
CU48  10U_0402_6.3V6M  [C_0402]  316.2 23.5 90 top
CV1  0.1U_0201_6.3V6K  [C_0201]  147.07 167.27 270 top
CV2  0.1U_0201_6.3V6K  [C_0201]  147.71 167.27 270 top
CV3  0.1U_0201_6.3V6K  [C_0201]  148.41 167.58 270 top
CV4  0.1U_0201_6.3V6K  [C_0201]  149.04 167.58 270 top
CV5  4.7U_0805_10V4Z  [C_0805]  161.93 164.73 90 bottom
CV6  0.1U_0201_6.3V6K  [C_0201]  150.31 167.58 270 top
CV7  0.1U_0201_6.3V6K  [C_0201]  150.57 166.19 270 top
CV8  0.1U_0201_6.3V6K  [C_0201]  149.68 167.58 270 top
CV9  0.1U_0402_10V7K  [C_0402]  164.47 169.98 0 bottom
CV10  4.7U_0805_10V4Z  [C_0805]  163.09 169.34 180 bottom
CV11  0.1U_0201_6.3V6K  [C_0201]  151.2 166.19 270 top
CV12  0.1U_0201_6.3V6K  [C_0201]  151.52 167.58 270 top
CV13  0.1U_0201_6.3V6K  [C_0201]  152.15 167.58 270 top
CV14  0.1U_0603_25V7K  [C_0603]  173.1 182.4 0 top
CV15  1000P_0402_50V7K  [C_0402]  152.79 168.32 270 bottom
CV17  0.1U_0402_10V7K  [C_0402]  164.47 169.03 0 bottom
CV18  10U_0603_6.3V6M  [C_0603]  162.89 167.86 180 bottom
CV19  0.1U_0402_10V7K  [C_0402]  166.98 171.9 180 bottom
CV20  0.1U_0402_16V7K  [C_0402]  223.11 160.04 90 bottom
CV21  4.7U_0805_10V4Z  [C_0805]  166.72 169.89 270 bottom
CV23  0.1U_0201_6.3V6K  [C_0201]  243.66 159.89 90 top
CV24  0.1U_0201_6.3V6K  [C_0201]  226.42 160.43 270 bottom
CV25  0.1U_0201_6.3V6K  [C_0201]  225.85 160.43 270 bottom
CV26  0.1U_0201_6.3V6K  [C_0201]  230.28 166.68 90 bottom
CV27  0.1U_0201_6.3V6K  [C_0201]  229.33 166.68 90 bottom
CV28  0.1U_0201_6.3V6K  [C_0201]  241.48 167.51 90 top
CV29  0.1U_0201_6.3V6K  [C_0201]  234.7 167.57 90 bottom
CV30  0.1U_0201_6.3V6K  [C_0201]  242.37 167.51 90 top
CV31  0.1U_0201_6.3V6K  [C_0201]  235.45 167.57 90 bottom
CV32  0.1U_0201_6.3V6K  [C_0201]  241.65 166.68 90 bottom
CV33  0.1U_0201_6.3V6K  [C_0201]  240.76 166.68 90 bottom
CV34  10U_0402_6.3V6M  [C_0402]  238.73 167.04 180 bottom
CV35  0.1U_0201_6.3V6K  [C_0201]  238.68 167.8 180 bottom
CV372  10P_0402_50V8J  [C_0402]  162.39 163.72 180 bottom
CV373  10P_0402_50V8J  [C_0402]  164.47 168.08 0 bottom
CV374  10P_0402_50V8J  [C_0402]  164.21 162.78 0 top
CV375  10P_0402_50V8J  [C_0402]  171.79 182.4 180 top
CV416  0.1U_0201_6.3V6K  [C_0201]  202.57 127.71 270 bottom
CV417  0.1U_0201_6.3V6K  [C_0201]  202 127.71 270 bottom
CV418  0.1U_0201_6.3V6K  [C_0201]  201.43 127.71 270 bottom
CV419  0.1U_0201_6.3V6K  [C_0201]  200.86 127.71 270 bottom
CV420  0.1U_0201_6.3V6K  [C_0201]  200.29 127.71 270 bottom
CV421  0.1U_0201_6.3V6K  [C_0201]  199.72 127.71 270 bottom
CV422  0.1U_0201_6.3V6K  [C_0201]  199.14 127.71 270 bottom
CV423  0.1U_0201_6.3V6K  [C_0201]  198.57 127.71 270 bottom
CV424  0.1U_0201_6.3V6K  [C_0201]  191.82 131.99 180 bottom
CV425  0.1U_0201_6.3V6K  [C_0201]  191.82 131.41 180 bottom
CV426  0.1U_0201_6.3V6K  [C_0201]  198 127.71 270 bottom
CV427  0.1U_0201_6.3V6K  [C_0201]  197.43 127.71 270 bottom
CV428  0.1U_0201_6.3V6K  [C_0201]  196.86 127.71 270 bottom
CV429  0.1U_0201_6.3V6K  [C_0201]  196.29 127.71 270 bottom
CV430  0.1U_0201_6.3V6K  [C_0201]  195.72 127.71 270 bottom
CV431  0.1U_0201_6.3V6K  [C_0201]  195.14 127.71 270 bottom
CV432  0.1U_0201_6.3V6K  [C_0201]  194.57 127.71 270 bottom
CV433  0.1U_0201_6.3V6K  [C_0201]  194 127.71 270 bottom
CV434  0.1U_0201_6.3V6K  [C_0201]  191.82 134.02 180 bottom
CV435  0.1U_0201_6.3V6K  [C_0201]  191.82 133.45 180 bottom
CV436  0.1U_0402_16V4Z  [C_0402]  192.5 130.15 270 bottom
CV437  0.1U_0402_16V4Z  [C_0402]  204.72 125.95 0 bottom
CV438  2.2U_0402_6.3V6M  [C_0402]  201.29 136.15 90 bottom
CV439  1U_0402_6.3V6K  [C_0402]  204.48 139.72 90 bottom
CV484  0.1U_0402_16V4Z  [C_0402]  126.62 155.61 0 top
CV1056  0.1U_0402_16V7K  [C_0402]  211.41 155.72 0 bottom
CV1057  0.1U_0201_6.3V6K  [C_0201]  218.3 164.22 270 bottom
CV1058  0.1U_0201_6.3V6K  [C_0201]  217.74 164.23 270 bottom
CV1059  0.1U_0201_6.3V6K  [C_0201]  212.91 164.27 270 bottom
CV1060  0.1U_0201_6.3V6K  [C_0201]  213.48 164.27 270 bottom
CV1061  0.1U_0201_6.3V6K  [C_0201]  215.34 164.24 270 bottom
CV1062  0.1U_0201_6.3V6K  [C_0201]  215.9 164.24 270 bottom
CV1063  0.1U_0201_6.3V6K  [C_0201]  210.52 164.28 270 bottom
CV1064  0.1U_0201_6.3V6K  [C_0201]  211.1 164.29 270 bottom
CV1068  10U_0603_6.3V6M~D  [C_0603]  222.26 169.32 0 bottom
CV1069  0.1U_0201_6.3V6K  [C_0201]  222.6 170.21 0 bottom
CX1  0.1U_0402_16V7K  [C_0402]  232.21 167.6 270 bottom
CX2  0.1U_0402_16V7K  [C_0402]  209.55 160.57 180 bottom
DA1  -  [BAT54C-7-F_SOT23-3]  38.35 25.43 270 top
DA2  BAT54AW_SOT323-3~D  [BAT54AW_SOT323-3]  36.86 22.57 90 bottom
DA3  BAT54AW_SOT323-3~D  [BAT54AW_SOT323-3]  35.14 41.4 180 top
DA4  AZ5125-02S.R7G_SOT23-3  [AZ5125-02SPR7G_SOT23-3]  22.45 18.19 270 bottom
DA5  AZ5123-02S SOT23  [AZ5125-02SPR7G_SOT23-3]  22.45 18.19 90 top
DA6  AZ5125-02S.R7G_SOT23-3  [AZ5125-02SPR7G_SOT23-3]  21.03 33.08 0 bottom
DA7  AZ5125-02S.R7G_SOT23-3  [AZ5125-02SPR7G_SOT23-3-NPM]  48.77 11.54 90 top
DA8  AZ5125-02S.R7G_SOT23-3  [AZ5125-02SPR7G_SOT23-3-NPM]  48.77 7.54 90 top
DE1  SDMK0340L-7-F_SOD323-2~D  [SDMK0340L-7-F_SOD323-2]  313.2 22.07 0 top
DE2  -  [RB751V-40_SOD323-2]  225.34 37.17 270 bottom
DE3  -  [RB751V-40_SOD323-2]  223.64 37.17 270 bottom
DE4  -  [RB751V-40_SOD323-2]  227.06 37.17 270 bottom
DF1  -  [SDMK0340L-7-F_SOD323-2]  102.93 59.78 270 top
DF2  -  [SDMK0340L-7-F_SOD323-2]  293.45 72.08 180 top
DG1  -  [BAT54A-7-F_SOT23-3]  199.84 115.39 180 bottom
DG2  -  [RB751S40T1G_SOD523-2]  215.21 110.78 0 bottom
DG3  -  [RB751S40T1G_SOD523-2]  281.58 170.99 270 top
DG4  -  [RB751S40T1G_SOD523-2]  212.96 159.18 0 top
DG6  -  [RB751S40T1G_SOD523-2]  277.67 165.09 270 top
DG7  -  [RB751S40T1G_SOD523-2]  281.58 167.43 90 top
DG8  -  [RB751S40T1G_SOD523-2]  188.22 34.39 180 bottom
DG9  -  [RB751S40T1G_SOD523-2]  188.22 36.8 180 bottom
DH1  -  [RB751V-40_SOD323-2]  223.78 27.27 90 bottom
DS1  SDM10U45-7_SOD523-2~D  [SDM10U45-7_SOD523-2]  188.09 64.87 0 top
DT1  SDM10U45-7_SOD523-2~D  [SDM10U45-7_SOD523-2]  190.74 175.7 90 top
DT2  ESD8011MUT5G X3DFN2 ESD  [ESD108-B1-CSP0201_WLL-2-1-2]  190.12 175.84 180 bottom
DT3  ESD8011MUT5G X3DFN2 ESD  [ESD108-B1-CSP0201_WLL-2-1-2]  190.78 175.84 0 bottom
DT4  ESD8011MUT5G X3DFN2 ESD  [ESD108-B1-CSP0201_WLL-2-1-2]  187.21 174.53 180 bottom
DT5  ESD8011MUT5G X3DFN2 ESD  [ESD108-B1-CSP0201_WLL-2-1-2]  187.91 174.53 0 bottom
DT6  ESD8011MUT5G X3DFN2 ESD  [ESD108-B1-CSP0201_WLL-2-1-2]  196.27 174.12 0 top
DT7  ESD8011MUT5G X3DFN2 ESD  [ESD108-B1-CSP0201_WLL-2-1-2]  195.61 174.12 180 top
DT8  ESD8011MUT5G X3DFN2 ESD  [ESD108-B1-CSP0201_WLL-2-1-2]  196.31 174.12 0 bottom
DT9  ESD8011MUT5G X3DFN2 ESD  [ESD108-B1-CSP0201_WLL-2-1-2]  195.61 174.12 180 bottom
DT10  -  [TVWDF1004AD0_DFN9]  191.81 174.37 0 bottom
DT11  ESD8011MUT5G X3DFN2 ESD  [ESD108-B1-CSP0201_WLL-2-1-2]  191.27 173.77 0 top
DT12  ESD8011MUT5G X3DFN2 ESD  [ESD108-B1-CSP0201_WLL-2-1-2]  196.9 175.89 90 top
DT13  ESD8011MUT5G X3DFN2 ESD  [ESD108-B1-CSP0201_WLL-2-1-2]  194.8 175.86 90 top
DT14  ESD8011MUT5G X3DFN2 ESD  [ESD108-B1-CSP0201_WLL-2-1-2]  188.54 176.12 180 top
DT15  AZ4024-02S_SOT23-3~D  [PESD24VS2UT_SOT23-3]  207.53 167.33 0 bottom
DU1  -  [L30ESDL5V0C3-2_SOT23-3]  20.37 36.99 90 bottom
DU2  -  [TVWDF1004AD0_DFN9]  20.23 37.49 90 top
DU6  -  [SDMK0340L-7-F_SOD323-2]  31.88 48.52 0 top
DU8  -  [SDMK0340L-7-F_SOD323-2]  34.16 46.29 270 top
DU11  -  [L30ESDL5V0C3-2_SOT23-3]  11.86 59.72 90 bottom
DU12  -  [TVWDF1004AD0_DFN9]  10.61 62.28 90 top
DU13  -  [TVWDF1004AD0_DFN9]  9.81 59.76 270 top
DU20  AZC199-02SPR7G_SOT23-3  [PSOT24C_SOT23-3]  15.12 63.79 270 bottom
DU21  AZC199-02SPR7G_SOT23-3  [PSOT24C_SOT23-3]  14.32 67.79 270 bottom
DV1  -  [RB751V-40_SOD323-2]  168.74 159.39 0 top
DV2  -  [PESD5V0U2BT_SOT23-3]  162.7 164.54 0 top
DV4  AZC199-02SPR7G_SOT23-3  [PSOT24C_SOT23-3]  166.95 164.54 0 top
DV12  -  [SDM10U45-7_SOD523-2]  223.02 166.4 90 bottom
DV13  -  [SDM10U45-7_SOD523-2]  221.62 166.4 90 bottom
DV14  AZC199-02SPR7G_SOT23-3  [PSOT24C_SOT23-3]  158.2 166.74 0 bottom
FD1  FIDUCIAL  [FIDUCIAL_C40M80]  280.68 153.07 90 top
FD2  FIDUCIAL  [FIDUCIAL_C40M80]  63.56 6.05 0 top
FD3  FIDUCIAL  [FIDUCIAL_C40M80]  29.54 13.3 180 bottom
FD4  FIDUCIAL  [FIDUCIAL_C40M80]  282.08 168.97 180 bottom
FD5  FIDUCIAL  [FIDUCIAL_C40M80]  334.81 5.33 0 top
FD6  FIDUCIAL  [FIDUCIAL_C40M80]  334.81 5.33 180 bottom
FV2  1.1A_6V_SPR-P110  [F_SPR-P110]  243.93 164.05 180 top
FV3  1.1A_6V_SPR-P110  [F_SPR-P110]  225.12 169.41 270 bottom
H1  -  [H_3P8]  160.17 155.6 0 top
H2  -  [H_3P8]  122.67 90.9 0 top
H3  -  [H_3P6]  181.67 90.3 0 top
H4  -  [H_3P8]  205.07 48.5 0 top
H5  -  [H_3P8]  276.07 43.5 0 top
H6  -  [H_3P0]  179.67 6.5 0 top
H7  -  [H_3P8]  269.07 150.5 0 top
H8  -  [H_3P0]  5.07 69.8 0 top
H9  -  [H_3P0]  6.57 50.8 0 top
H10  -  [H_3P0]  28.07 54 0 top
H11  -  [H_3P6]  22.07 11.5 0 top
H12  -  [H_3P0]  276.17 170.6 0 top
H13  -  [H_3P6X4P2]  199.57 152 0 top
H14  -  [H_3P0]  202.22 180.1 0 top
H15  -  [H_3P0]  183.22 180.1 0 top
H16  -  [H_3P0]  22.07 4.2 0 top
H17  -  [H_3P0]  144.57 171.5 0 top
H18  -  [H_3P0]  102.07 6.5 0 top
H19  -  [H_3P0]  92.87 56.9 0 top
H20  -  [H_3P0]  297.87 76.25 0 top
H21  -  [H_3P0]  262.07 6.5 0 top
H22  -  [H_3P0]  197.87 55.6 0 top
H23  -  [H_4P1X3P6]  267.97 6.5 0 top
J4  -  [JUMP_43X79]  58.75 12.51 90 bottom
J5  -  [JUMP_43X79]  70.66 14.07 180 bottom
J6  -  [JUMP_43X79]  225.39 38.01 0 top
JACK1  YUQIU_PJ741-F07J1BE-C  [YUQIU_PJ741-F07J1BE-C_6P-T]  13.47 4.3 90 bottom
JACK2  YUQIU_PJ741-F07J1BE-C  [YUQIU_PJ741-F07J1BE-C_6P-T]  13.47 17 90 bottom
JCDRA  TE_2260531-1  [TE_2260531-1_46P-T]  151.87 177.71 0 bottom
JDIMM1  DEREN_40-42271-26001RHF  [DEREN_40-42271-26001RHF_260P-T]  111.69 60 0 bottom
JDIMM2  DEREN_40-42261-26001RHF  [DEREN_40-42261-26001RHF_260P-T]  111.69 47.2 180 bottom
JDP  ACON_MAR2F-20K1800  [ACON_MAR2F-20K1800_20P]  232.37 173.69 180 bottom
JEC  ACES_50521-0084N-P01  [ACES_50521-0084N-P01_8P]  284.31 8.44 270 bottom
JEDP  ACES_50473-0400M-P01  [ACES_50473-0400M-P01_40P]  151.62 180.27 0 top
JELC  AMPHE_G846A06201EU  [AMPHE_G846A06201EU_6P-T]  166.6 26.54 0 bottom
JFAN1  ACES_50278-00401-001  [ACES_50278-00401-001_4P]  106.87 63.3 180 top
JFAN2  ACES_50278-00401-001  [ACES_50278-00401-001_4P]  290.87 77.25 180 top
JHDD  STARC_111H30-000000-G4-R  [STARC_111H30-000000-G4-R_30P]  113.42 9.95 0 bottom
JHDMI  ACON_HMRA3-AK1L0C  [ACON_HMRA3-AK1L0C_19P]  212.12 174.3 0 bottom
JIO  ACES_50473-0300M-P01  [ACES_50473-0300M-P01_30P]  325.55 9.85 90 top
JKB  ACES_50552-03001-P01  [ACES_50552-03001-P01_30P]  223.47 7.75 180 bottom
JKB2  -  [ACES_50611-0100N-001_10P]  139.38 8.68 0 bottom
JKB3  ACES_87153-06411  [ACES_87153-06411_6P]  64.93 4.93 180 bottom
JKBBL  ACES_50552-02001-P01  [ACES_50552-02001-P01_20P]  169.82 7.75 180 bottom
JLAN  SANTA_130456-512  [SANTA_130456-512_13P]  249.64 171.77 0 bottom
JLOGO  ACES_87212-1600L  [ACES_87212-1600L_16P]  221.92 166.19 0 top
JP1  PAD-OPEN 43X39  [JUMP_43X39]  198 44.06 270 top
JP2  PAD-OPEN 43X39  [JUMP_43X39]  203.27 42.53 270 top
JP3  -  [JUMP_43X118]  130.61 9.24 180 top
JPCMC  INTEL_CMC_PRIMARY  [INTEL_CMC_PRIMARY_36P-T]  122.87 157.33 270 top
JPWR  ACES_87153-06411  [ACES_87153-06411_6P]  210.32 166.12 0 top
JRTC1  ACES_50271-00201-001  [ACES_50271-00201-001_2P]  292.69 37.1 180 bottom
JSPK  ACES_50278-00601-001  [ACES_50278-00601-001_6P-T]  52.18 14.16 180 bottom
JSSD1  LCN_DAN05-67406-0103  [LCN_DAN05-67406-0103_75P-T]  325.85 48.11 270 bottom
JSSD2  LCN_DAN05-67406-0103  [LCN_DAN05-67406-0103_75P-T]  271.85 24.25 270 bottom
JSSD3  LCN_DAN05-67406-0103  [LCN_DAN05-67406-0103_75P-T]  254.02 12.92 180 bottom
JTOBII  ACES_50450-0067N-P01  [ACES_50450-0067N-P01_6P]  154.56 165.75 0 top
JTP  ACES_51522-01601-P01  [ACES_51522-01601-P01_16P]  196.82 11.1 180 bottom
JTRONL  ACES_50450-0127N-001  [ACES_50450-0127N-001_12P]  43.47 49.25 180 bottom
JTRONR  ACES_50450-0127N-001  [ACES_50450-0127N-001_12P]  274.77 30.6 0 bottom
JUSB1  SDAN_608015-010232  [SDAN_608015-010232_10P]  16.55 41.4 90 bottom
JUSBC1  -  [JAE_DX07S024JJ5_24P-T]  190.1 178 0 bottom
JUSBC2  -  [JAE_DX07S024JJ5_24P-T]  7.55 62.92 270 top
JWDB  ACES_88266-04001  [ACES_50207-00471-P01_4P-T]  205.49 10.42 0 top
JWLAN  LCN_DAN05-67306-0102  [LCN_DAN05-67306-0102_67P]  300.32 33.57 0 bottom
LA3  BLM15AG121SN1D_L0402_2P  [MURAT_BLM15AG121SN1D_L0402_2P]  33.82 21.81 0 bottom
LA4  BLM15AG121SN1D_L0402_2P  [MURAT_BLM15AG121SN1D_L0402_2P]  30.83 21.76 0 bottom
LA5  BLM15AG121SN1D_L0402_2P  [MURAT_BLM15AG121SN1D_L0402_2P]  40.8 30.9 90 top
LA6  BLM15BB221SN1D_2P  [MURAT_BLM15BB221SN1D_2P]  35.8 37.05 180 bottom
LA7  BLM15PX330SN1D 0402  [MURAT_BLM15BD601SN1D_2P]  26.93 18.76 180 bottom
LA8  BLM15PX330SN1D 0402  [MURAT_BLM15BD601SN1D_2P]  27.76 20.92 0 top
LA9  FBMA-L11-160808-800LMT_2P  [KC_FBMA-L10-160808-800LMT_2P]  24.52 18.56 270 bottom
LA10  FBMA-L11-160808-800LMT_2P  [KC_FBMA-L10-160808-800LMT_2P]  17.42 23.23 270 bottom
LA11  BLM15PX330SN1D 0402  [MURAT_BLM15BD601SN1D_2P]  21.93 22.25 0 top
LA12  BLM15PX330SN1D 0402  [MURAT_BLM15BD601SN1D_2P]  21.93 23.9 0 top
LA50  BLM15PX121SN1D_2P  [MURAT_BLM15PX121SN1D_2P]  37.21 4.1 270 top
LA51  BLM15PX121SN1D_2P  [MURAT_BLM15PX121SN1D_2P]  36.71 3.21 180 bottom
LA52  BLM15PX121SN1D_2P  [MURAT_BLM15PX121SN1D_2P]  32.51 3.08 270 top
LA53  BLM15PX121SN1D_2P  [MURAT_BLM15PX121SN1D_2P]  30.99 4.41 180 top
LE1  FBMA-L11-160808-800LMT_0603  [KC_FBMA-L11-160808-800LMT_2P]  289.23 25.67 180 top
LE2  FBMA-L11-160808-800LMT_0603  [KC_FBMA-L11-160808-800LMT_2P]  286.08 9.87 0 top
LE3  MCM1012B900F06BP_4P  [INPAQ_MCM1012B900F06BP_4P-NPM]  156.91 161.46 90 bottom
LG1  PBY160808T-301Y-N  [CHILI_PBY160808T-300Y-N_2P]  219.67 109 180 top
LG2  PBY160808T-300Y-N_2P  [CHILI_PBY160808T-300Y-N_2P]  203.53 106.25 90 top
LG3  PBY160808T-300Y-N_2P  [CHILI_PBY160808T-300Y-N_2P]  225.62 117.59 270 top
LG4  PBY160808T-301Y-N  [CHILI_PBY160808T-300Y-N_2P]  222.89 117.59 270 top
LG5  PBY160808T-300Y-N_2P  [CHILI_PBY160808T-300Y-N_2P]  224.53 120.62 0 top
LG6  PBY160808T-300Y-N_2P  [CHILI_PBY160808T-300Y-N_2P]  202.07 106.25 90 top
LL1  BLM15AG121SN1D_L0402_2P  [MURAT_BLM15AG121SN1D_L0402_2P]  265.88 156.39 90 top
LM1  MCM1012B900F06BP_4P  [INPAQ_MCM1012B900F06BP_4P]  168.47 173.27 90 bottom
LT1  0.6UH_MND-04ABIR60M-XGL_20%  [MAG_MND-04ABIR60M-XGL_2P]  173.3 168.85 90 bottom
LT2  MCM1012B900F06BP_4P  [INPAQ_MCM1012B900F06BP_4P]  192.27 170.89 90 bottom
LT3  MCM1012B900F06BP_4P  [INPAQ_MCM1012B900F06BP_4P]  193.85 170.89 90 bottom
LU3  MCM1012B900F06BP_4P  [INPAQ_MCM1012B900F06BP_4P]  23.25 40.85 270 bottom
LU4  HCM1012GD670A05P  [INPAQ_MCM1012B900F06BP_4P]  22.9 39 180 top
LU5  HCM1012GD670A05P  [INPAQ_MCM1012B900F06BP_4P]  22.9 37.48 180 top
LU7  HCM1012GD670A05P  [INPAQ_MCM1012B900F06BP_4P]  13.28 62.25 180 top
LU8  HCM1012GD670A05P  [INPAQ_MCM1012B900F06BP_4P]  13.28 63.84 180 top
LU9  MCM1012B900F06BP_4P  [INPAQ_MCM1012B900F06BP_4P]  16.16 58.02 90 bottom
LU10  HCM1012GD670A05P  [INPAQ_MCM1012B900F06BP_4P]  13.47 57.82 180 top
LU11  HCM1012GD670A05P  [INPAQ_MCM1012B900F06BP_4P]  13.47 59.28 180 top
LV2  MCM1012B900F06BP_4P  [INPAQ_MCM1012B900F06BP_4P]  167.02 161.4 90 top
LV3  HCM1012GH900BP_4P  [INPAQ_HCM1012GH900BP_4P-NPM]  218.22 165.65 90 bottom
LV4  HCM1012GH900BP_4P  [INPAQ_HCM1012GH900BP_4P-NPM]  213.42 165.65 90 bottom
LV5  HCM1012GH900BP_4P  [INPAQ_HCM1012GH900BP_4P-NPM]  215.83 165.65 90 bottom
LV6  HCM1012GH900BP_4P  [INPAQ_HCM1012GH900BP_4P-NPM]  211.03 165.65 90 bottom
LX1  PBY100505T-601Y-N_2P  [CHILI_PBY100505T-300Y-N_2P]  214.54 161.13 270 top
LX2  PBY100505T-601Y-N_2P  [CHILI_PBY100505T-300Y-N_2P]  213.39 161.13 270 top
LX3  PBY100505T-601Y-N_2P  [CHILI_PBY100505T-300Y-N_2P]  219.17 161.09 270 top
LX4  PBY100505T-601Y-N_2P  [CHILI_PBY100505T-300Y-N_2P]  218.02 161.09 270 top
LX5  PBY100505T-601Y-N_2P  [CHILI_PBY100505T-300Y-N_2P]  216.85 161.16 270 top
LX6  PBY100505T-601Y-N_2P  [CHILI_PBY100505T-300Y-N_2P]  215.69 161.16 270 top
LX7  PBY100505T-601Y-N_2P  [CHILI_PBY100505T-300Y-N_2P]  212.24 161.13 270 top
LX8  PBY100505T-601Y-N_2P  [CHILI_PBY100505T-300Y-N_2P]  211.1 161.13 270 top
NOREF  -  []  276.17 170.6 0 top
NOREF#2  -  []  102.07 6.5 0 top
NOREF#3  -  []  205.07 48.5 0 top
NOREF#4  -  []  199.57 152 0 top
NOREF#5  -  []  276.07 43.5 0 top
NOREF#6  -  []  28.07 54 0 top
NOREF#7  -  []  179.67 6.5 0 top
NOREF#8  -  []  122.67 90.9 0 top
NOREF#9  -  []  197.87 55.6 0 top
NOREF#10  -  []  140.14 25.25 90 top
NOREF#11  -  []  269.07 150.5 0 top
NOREF#12  -  []  181.67 90.3 0 top
NOREF#13  -  []  144.57 171.5 0 top
NOREF#14  -  []  109.74 238.16 0 top
NOREF#15  -  []  124.84 32.44 0 top
NOREF#16  -  []  92.87 56.9 0 top
NOREF#17  -  []  88.35 10.2 0 top
NOREF#18  -  []  153.78 17.34 0 top
NOREF#19  -  []  297.87 76.25 0 top
NOREF#20  -  []  150.75 -28.39 0 top
NOREF#21  -  []  160.17 155.6 0 top
NOREF#22  -  []  120.07 72.85 0 top
NOREF#23  -  []  250.86 40.75 0 top
NOREF#24  -  []  153.83 67.81 0 top
NOREF#25  -  []  335.29 17.81 180 bottom
NOREF#26  -  []  258.25 74.8 180 bottom
PBATT1  ACES_50290-01201-P01  [ACES_50290-01201-P01_12P-T]  91.82 13.95 180 bottom
PC1  1000P_0402_50V7K  [C_0402]  84.1 37.75 90 bottom
PC2  100P_0402_50V8J  [C_0402]  85.2 37.72 90 bottom
PC3  1000P_0402_50V7K  [C_0402]  75.57 32.7 270 bottom
PC4  100P_0402_50V8J  [C_0402]  74.68 32.7 270 bottom
PC6  0.022U_0402_25V7K  [C_0402]  88.4 26.77 90 bottom
PC7  0.01UF_0402_25V7K  [C_0402]  87.51 26.77 90 bottom
PC8  1000P_0402_50V7K  [C_0402]  83.08 20.21 180 top
PC9  100P_0402_50V8J  [C_0402]  83.07 19.27 180 top
PC10  0.22U_0603_25V7K  [C_0603]  73.73 9.37 180 top
PC11  0.1U_0402_25V6  [C_0402]  67 13.61 90 top
PC12  .1U_0402_16V7K  [C_0402]  68.88 8.19 270 top
PC13  .1U_0402_16V7K  [C_0402]  293.21 6.32 270 top
PC14  1U_0603_25V6K  [C_0603]  82.41 7.82 180 top
PC100  0.1U_0402_25V6  [C_0402]  45.96 40.92 180 top
PC101  4.7U_0603_6.3V6K  [C_0603]  53.95 48.56 90 bottom
PC102  22U_0805_25V6M  [C_0805]  52.4 33.81 180 top
PC103  2200P_0402_50V7K  [C_0402]  45.97 41.81 180 top
PC104  22U_0805_25V6M  [C_0805]  48.27 38.73 270 top
PC105  0.1U_0402_25V6  [C_0402]  57.53 45.75 0 bottom
PC106  0.1U_0402_25V6  [C_0402]  49.2 45.61 0 bottom
PC108  220U_D2_6.3VY_R15M  [C_D2]  37.69 39.91 180 bottom
PC109  680P_0603_50V8J  [C_0603]  43.76 30.8 0 top
PC110  680P_0603_50V8J  [C_0603]  44.08 32 0 top
PC111  4.7U_0603_6.3V6K  [C_0603]  53.73 42.32 0 bottom
PC112  4.7U_0603_6.3V6K  [C_0603]  61.65 47.28 0 top
PC113  22U_0805_25V6M  [C_0805]  50.05 38.73 270 top
PC114  22U_0805_25V6M  [C_0805]  52.39 35.58 180 top
PC115  220U_D2_6.3VY_R15M  [C_D2]  37.69 44.67 180 bottom
PC116  220U_D2_6.3VY_R15M  [C_D2]  42.3 18.76 180 bottom
PC117  220U_D2_6.3VY_R15M  [C_D2]  41.86 23.21 90 bottom
PC118  1U_0402_25V6K  [C_0402]  53.94 31.91 270 top
PC119  1000P_0402_50V7K  [C_0402]  54.93 31.91 270 top
PC200  0.1U_0402_25V6  [C_0402]  92.72 33.36 0 top
PC201  2200P_0402_50V7K  [C_0402]  92.72 34.25 0 top
PC202  10U_0805_25V6K~D  [C_0805]  92.73 32.37 270 top
PC203  10U_0805_25V6K~D  [C_0805]  91.03 32.48 270 top
PC204  0.1U_0603_25V7K  [C_0603]  88.21 42.01 0 bottom
PC205  10U_0805_6.3V6K  [C_0805]  91.41 47.53 180 bottom
PC206  10U_0805_6.3V6K  [C_0805]  91.41 49.37 180 bottom
PC207  1U_0603_10V6K  [C_0603]  93.61 39.4 90 bottom
PC208  1U_0402_25V6K  [C_0402]  88.64 35.15 90 top
PC209  220U_D2 SX_2VY_R9M  [C_D2]  96.27 29.05 270 bottom
PC210  0.033U_0402_16V7K  [C_0402]  92.91 47.14 90 bottom
PC211  680P_0402_50V7K  [C_0402]  97.27 34.28 180 top
PC212  1U_0603_10V6K  [C_0603]  94.94 40.8 270 bottom
PC213  0.1U_0402_10V7K  [C_0402]  95.88 44.55 0 bottom
PC214  0.1U_0402_10V7K  [C_0402]  95.88 45.43 0 bottom
PC215  220U_D2 SX_2VY_R9M  [C_D2]  91.41 29.14 270 bottom
PC216  1000P_0402_50V7K  [C_0402]  87.72 35.15 90 top
PC217  0.1U_0402_25V6  [C_0402]  103.17 51.9 270 top
PC218  0.1U_0402_25V6  [C_0402]  107.9 54.65 270 top
PC300  0.1U_0402_16V7K  [C_0402]  241.83 16.03 180 top
PC301  0.1U_0402_25V6  [C_0402]  259.2 21.24 0 top
PC302  2200P_0402_50V7K  [C_0402]  259.2 20.35 0 top
PC303  10U_0805_25V6K~D  [C_0805]  260.08 18.07 180 top
PC304  10U_0805_25V6K~D  [C_0805]  260.08 16.35 180 top
PC305  0.1U_0603_25V7K  [C_0603]  248.29 18.96 270 top
PC306  220U_D2 SX_2VY_R9M  [C_D2]  244.59 22.79 270 bottom
PC307  220U_D2 SX_2VY_R9M  [C_D2]  239.82 22.79 270 bottom
PC308  1U_0603_6.3V6M  [C_0603]  247.85 16.48 270 top
PC309  680P_0402_50V7K  [C_0402]  257.49 17.3 0 bottom
PC310  1U_0402_25V6K  [C_0402]  259.2 19.46 0 top
PC311  1000P_0402_50V7K  [C_0402]  259.2 22.13 0 top
PC500  330P_0402_50V7K  [C_0402]  124.42 138.46 180 top
PC501  47P_0402_50V8J~D  [C_0402]  124.06 133.79 270 bottom
PC502  0.1U_0402_25V6  [C_0402]  124.05 132.87 90 top
PC503  1U_0402_16V6K  [C_0402]  126.5 137.57 90 top
PC504  0.22U_0603_25V7K  [C_0603]  127.64 137.89 90 top
PC505  68P_0402_50V8J  [C_0402]  123.95 139.62 180 top
PC506  6800P_0402_25V7K  [C_0402]  123.95 140.51 180 top
PC507  1000P_0402_50V7K  [C_0402]  119.55 137.03 270 bottom
PC508  470P_0402_50V7K  [C_0402]  121.34 137.02 180 bottom
PC509  2200P_0402_50V7K  [C_0402]  132.15 137.56 90 bottom
PC510  0.01UF_0402_25V7K  [C_0402]  133.09 141.12 180 bottom
PC511  .1U_0402_16V7K  [C_0402]  129.61 136.06 270 top
